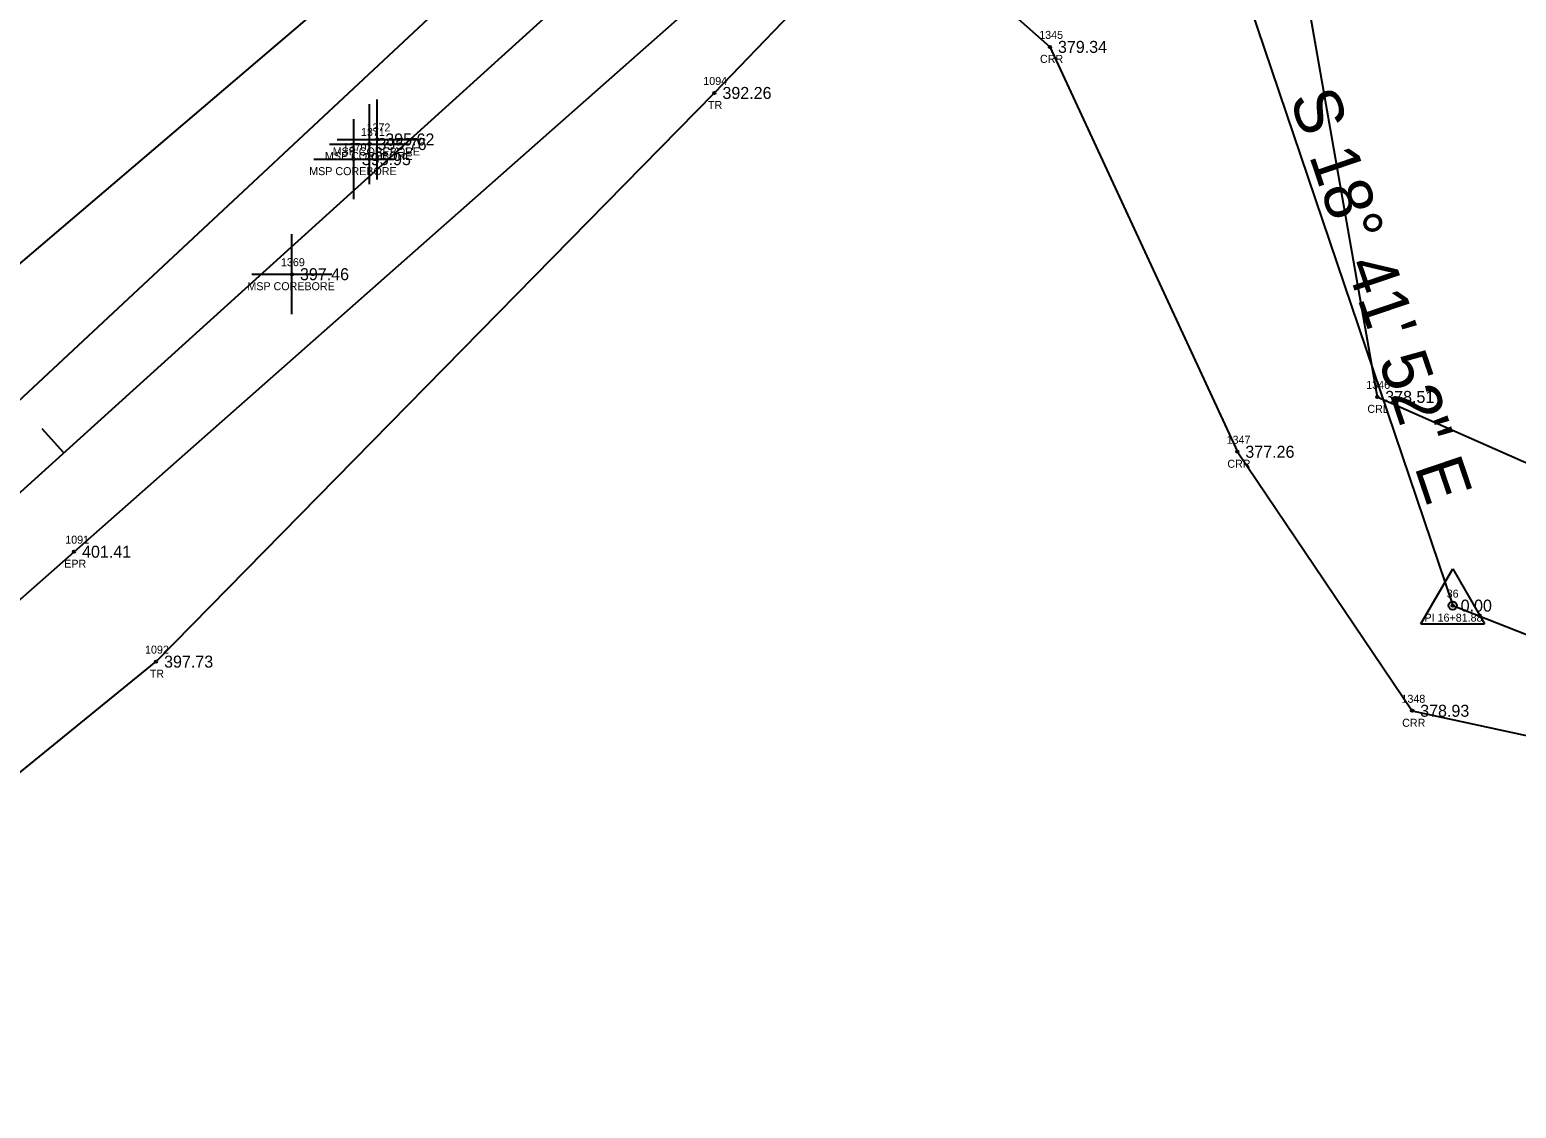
# Model space of a CAD drawing. Extents: x 2116015 to 2118228, y 979206 to 981145.
# Drawn here: x 2117252 to 2117437.8, y 979979.7 to 980114.5 of the extents above; entities that cross this region are included whole.
import ezdxf

# ---------------------------------------------------------------- set-up
doc = ezdxf.new("R2010")
doc.units = 0
for name, color, linetype in [('RD_EX_H2O', 7, 'Continuous'), ('RD_EX_H2O_txCode', 7, 'Continuous'), ('RD_EX_Misc', 7, 'Continuous'), ('RD_EX_Misc_txCode', 7, 'Continuous'), ('RD_EX_Road', 7, 'Continuous'), ('RD_EX_Road_txCode', 7, 'Continuous'), ('RD_EX_TX_H2O_ELEV', 7, 'Continuous'), ('RD_EX_TX_Misc_ELEV', 7, 'Continuous'), ('RD_EX_TX_Road_ELEV', 7, 'Continuous'), ('RD_EX_TX_VEG_ELEV', 7, 'Continuous'), ('RD_EX_VEG', 7, 'Continuous'), ('RD_EX_VEG_txCode', 7, 'Continuous'), ('RD_HC_Cl', 7, 'Continuous'), ('RD_HC_Data', 7, 'Continuous'), ('RD_HC_Data_Tic', 7, 'Continuous'), ('RD_HC_Survey_ELEV', 7, 'Continuous'), ('RD_HC_txCode', 7, 'Continuous'), ('RD_SMD_Locator', 7, 'Continuous')]:
    doc.layers.add(name, color=color, linetype=linetype)

msp = doc.modelspace()

# ---------------------------------------------------------------- linework, layer by layer
at = {"layer": 'RD_EX_H2O'}
for points in [[(2117055.27, 980533.4), (2117084.87, 980468.5), (2117113.12, 980396.82), (2117150.26, 980360.48), (2117172.14, 980330.53), (2117167.4, 980300.56), (2117152, 980282.05), (2117153.33, 980268.31), (2117164.01, 980260.72), (2117221.6, 980247.26), (2117265.25, 980211.02), (2117324.27, 980199.15), (2117347.37, 980175.31), (2117365.85, 980182.55), (2117389.45, 980162.29), (2117399.63, 980142.01), (2117411.26, 980120.88), (2117420.42, 980068.64), (2117446.24, 980057.21), (2117497.11, 980045.39), (2117594.71, 979999.33), (2117646.33, 979985.56), (2117750.91, 980032.44), (2117805.09, 980018.87)], [(2117253.76, 980181.57), (2117309.73, 980180.01), (2117328.75, 980169.13), (2117302.89, 980172.19), (2117303.47, 980157.54), (2117331.87, 980146.51), (2117356.54, 980132.72), (2117379.52, 980112.38), (2117402.94, 980061.78), (2117424.79, 980029.41), (2117490.12, 980015.27), (2117551.05, 979984.61)]]:
    msp.add_lwpolyline(points, dxfattribs=at)
at = {"layer": 'RD_EX_Misc'}
for p, q in [((2117294.48, 980095.24), (2117294.48, 980105.24)), ((2117295.45, 980095.81), (2117295.45, 980105.81)), ((2117292.52, 980093.35), (2117292.52, 980103.35)), ((2117289.48, 980100.24), (2117299.48, 980100.24)), ((2117290.45, 980100.81), (2117300.45, 980100.81)), ((2117287.52, 980098.35), (2117297.52, 980098.35)), ((2117284.79, 980078.97), (2117284.79, 980088.97)), ((2117279.79, 980083.97), (2117289.79, 980083.97))]:
    msp.add_line(p, q, dxfattribs=at)
at = {"layer": 'RD_EX_Road'}
for points in [[(2116412.2, 979638.84), (2116468.17, 979651.36), (2116519.2, 979662.5), (2116617.24, 979678.85), (2116665.51, 979689.1), (2116714.23, 979702.46), (2116761.42, 979719.35), (2116806.99, 979737.42), (2116852.23, 979758.11), (2116896.57, 979780.91), (2116939.1, 979805.52), (2116978.46, 979832.1), (2117021.29, 979863.87), (2117058.15, 979895.61), (2117096.06, 979930.47), (2117170.14, 979995.71), (2117244.91, 980062.82), (2117320.63, 980133.49), (2117326.56, 980126.36)], [(2116416.36, 979621.21), (2116470.51, 979634.11), (2116523.97, 979644.68), (2116620.55, 979661.21), (2116670.7, 979671.96), (2116720.65, 979685.84), (2116767.66, 979702.22), (2116814.07, 979721.02), (2116860.35, 979742.3), (2116904.9, 979765.18), (2116949.06, 979791.19), (2116988.09, 979817.15), (2117031.94, 979849.78), (2117069.79, 979881.53), (2117108.89, 979916.38), (2117182.06, 979982.67), (2117257.56, 980049.29), (2117334.73, 980117.38), (2117326.56, 980126.36)]]:
    msp.add_lwpolyline(points, dxfattribs=at)
at = {"layer": 'RD_EX_VEG'}
for points in [[(2116722.45, 979669.37), (2116774.18, 979691.43), (2116821.78, 979704.49), (2116866.89, 979731.28), (2116911.37, 979756.82), (2116957.81, 979781.77), (2116997.88, 979803.71), (2117039.1, 979840.44), (2117073.79, 979876.07), (2117114.06, 979911.54), (2117190.83, 979972.91), (2117267.81, 980035.55), (2117337.59, 980106.62), (2117402.21, 980173.85), (2117485.32, 980246.56), (2117565.74, 980310.34), (2117637.66, 980378.54), (2117750.19, 980480.17), (2117790.07, 980510.8), (2117823.1, 980550.79), (2117858.05, 980587.85), (2117890.76, 980626.84)], [(2116712.02, 979710.38), (2116759.23, 979727.55), (2116802.24, 979746.7), (2116849.22, 979766.16), (2116893.59, 979788.48), (2116935.29, 979812.54), (2116975.95, 979836.39), (2117019.34, 979866.44), (2117054.55, 979897.64), (2117091.93, 979934.98), (2117160.1, 980005.89), (2117234.47, 980071.39), (2117310.73, 980136.42), (2117382.56, 980200.01), (2117453.09, 980281.19), (2117606.26, 980413.06), (2117681.92, 980479.39), (2117728.74, 980526.62), (2117785.53, 980582.83), (2117819.37, 980618.82)]]:
    msp.add_lwpolyline(points, dxfattribs=at)
at = {"layer": 'RD_HC_Cl'}
for p, q in [((2117075.77, 979898.29), (2117736.78, 980496.56)), ((2117404.48, 980117.53), (2117429.85, 980042.55)), ((2117429.85, 980042.55), (2117583.13, 979982.49))]:
    msp.add_line(p, q, dxfattribs=at)
at = {"layer": 'RD_HC_Data'}
for p, q in [((2117425.88, 980040.26), (2117429.85, 980047.14)), ((2117429.85, 980047.14), (2117433.82, 980040.26)), ((2117425.88, 980040.26), (2117433.82, 980040.26))]:
    msp.add_line(p, q, dxfattribs=at)
msp.add_circle((2117429.85, 980042.55), 0.529, dxfattribs=at)
at = {"layer": 'RD_HC_Data_Tic'}
msp.add_line((2117256.27, 980061.66), (2117253.59, 980064.63), dxfattribs=at)
at = {"layer": 'RD_SMD_Locator'}
for centre in [(2117379.52, 980112.38), (2117337.59, 980106.62), (2117294.48, 980100.24), (2117295.45, 980100.81), (2117292.52, 980098.35), (2117284.79, 980083.97), (2117420.42, 980068.64), (2117402.94, 980061.78), (2117257.56, 980049.29), (2117429.85, 980042.55), (2117267.81, 980035.55), (2117424.79, 980029.41)]:
    msp.add_circle(centre, 0.15, dxfattribs=at)

# ---------------------------------------------------------------- texts
at = {"layer": 'RD_EX_H2O_txCode'}
for s, p in [('1345', (2117378.18, 980113.38)), ('CRR', (2117378.27, 980110.38)), ('1346', (2117419.05, 980069.64)), ('CRL', (2117419.19, 980066.64)), ('1347', (2117401.6, 980062.78)), ('CRR', (2117401.69, 980059.78)), ('1348', (2117423.45, 980030.41)), ('CRR', (2117423.54, 980027.41))]:
    msp.add_text(s, height=1, dxfattribs=at).set_placement(p)
at = {"layer": 'RD_EX_Misc_txCode'}
for s, p in [('1371', (2117293.42, 980101.24)), ('1372', (2117294.11, 980101.81)), ('MSP COREBORE', (2117289.88, 980098.81)), ('1370', (2117291.13, 980099.35)), ('MSP COREBORE', (2117288.91, 980098.24)), ('MSP COREBORE', (2117286.95, 980096.35)), ('1369', (2117283.42, 980084.97)), ('MSP COREBORE', (2117279.22, 980081.97))]:
    msp.add_text(s, height=1, dxfattribs=at).set_placement(p)
at = {"layer": 'RD_EX_Road_txCode'}
for s, p in [('1091', (2117256.46, 980050.29)), ('EPR', (2117256.33, 980047.29))]:
    msp.add_text(s, height=1, dxfattribs=at).set_placement(p)
at = {"layer": 'RD_EX_TX_H2O_ELEV'}
for s, p in [('379.34', (2117380.52, 980111.63)), ('378.51', (2117421.42, 980067.89)), ('377.26', (2117403.94, 980061.03)), ('378.93', (2117425.79, 980028.66))]:
    msp.add_text(s, height=1.5, dxfattribs=at).set_placement(p)
at = {"layer": 'RD_EX_TX_Misc_ELEV'}
for s, p in [('395.62', (2117296.45, 980100.06)), ('395.76', (2117295.48, 980099.49)), ('395.95', (2117293.52, 980097.6)), ('397.46', (2117285.79, 980083.22))]:
    msp.add_text(s, height=1.5, dxfattribs=at).set_placement(p)
at = {"layer": 'RD_EX_TX_Road_ELEV'}
msp.add_text('401.41', height=1.5, dxfattribs=at).set_placement((2117258.56, 980048.54))
at = {"layer": 'RD_EX_TX_VEG_ELEV'}
for s, p in [('392.26', (2117338.59, 980105.87)), ('397.73', (2117268.81, 980034.8))]:
    msp.add_text(s, height=1.5, dxfattribs=at).set_placement(p)
at = {"layer": 'RD_EX_VEG_txCode'}
for s, p in [('1094', (2117336.2, 980107.62)), ('TR', (2117336.79, 980104.62)), ('1092', (2117266.43, 980036.55)), ('TR', (2117267.02, 980033.55))]:
    msp.add_text(s, height=1, dxfattribs=at).set_placement(p)
at = {"layer": 'RD_HC_Data'}
msp.add_text('S 18%%d 41\' 52" E', height=6, rotation=288.6979, dxfattribs=at).set_placement((2117409.44, 980105.98))
at = {"layer": 'RD_HC_Survey_ELEV'}
msp.add_text('0.00', height=1.5, dxfattribs=at).set_placement((2117430.85, 980041.8))
at = {"layer": 'RD_HC_txCode'}
for s, p in [('36', (2117429.1, 980043.55)), ('PI 16+81.88', (2117426.33, 980040.55))]:
    msp.add_text(s, height=1, dxfattribs=at).set_placement(p)

doc.saveas('drawing.dxf')
